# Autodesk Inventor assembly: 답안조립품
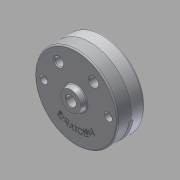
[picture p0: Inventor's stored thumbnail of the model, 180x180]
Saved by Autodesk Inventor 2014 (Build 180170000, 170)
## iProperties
Created: 2015-06
Part Number: 답안조립품
Document SubType Name: Assembly
Designer: MYHOME
Author: MYHOME
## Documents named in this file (4)
- C:\Documents and Settings\MYHOME\바탕 화면\450631V1039\450631V1039\답안조립품.iam
- C:\Documents and Settings\MYHOME\바탕 화면\450631V1039\본체.ipt
- C:\Documents and Settings\MYHOME\바탕 화면\450631V1039\450631V1039\덮개.ipt
- C:\Documents and Settings\MYHOME\바탕 화면\450631V1039\450631V1039\베어링62_22.ipt
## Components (2 placed, 1 different names)
1. KS B 2023 62/22 - 22 x 50 x 14:1
2. KS B 2023 62/22 - 22 x 50 x 14:2
